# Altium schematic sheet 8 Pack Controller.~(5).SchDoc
size B; PageSetup: Record=PageOptions|CenterHorizontal=True|CenterVertical=True|PrintScale=1.09|XCorrection=1.00|YCorrection=1.00|PrintKind=0|BorderSize=5000000|LeftOffset=0|BottomOffset=0|Orientation=2|PaperLength=1000|PaperWidth=1000|Scale=100|PaperSource=15|PrintQuality=600|MediaType=1|DitherType=10|PaperKind=11x17|PrintScaleMode=1
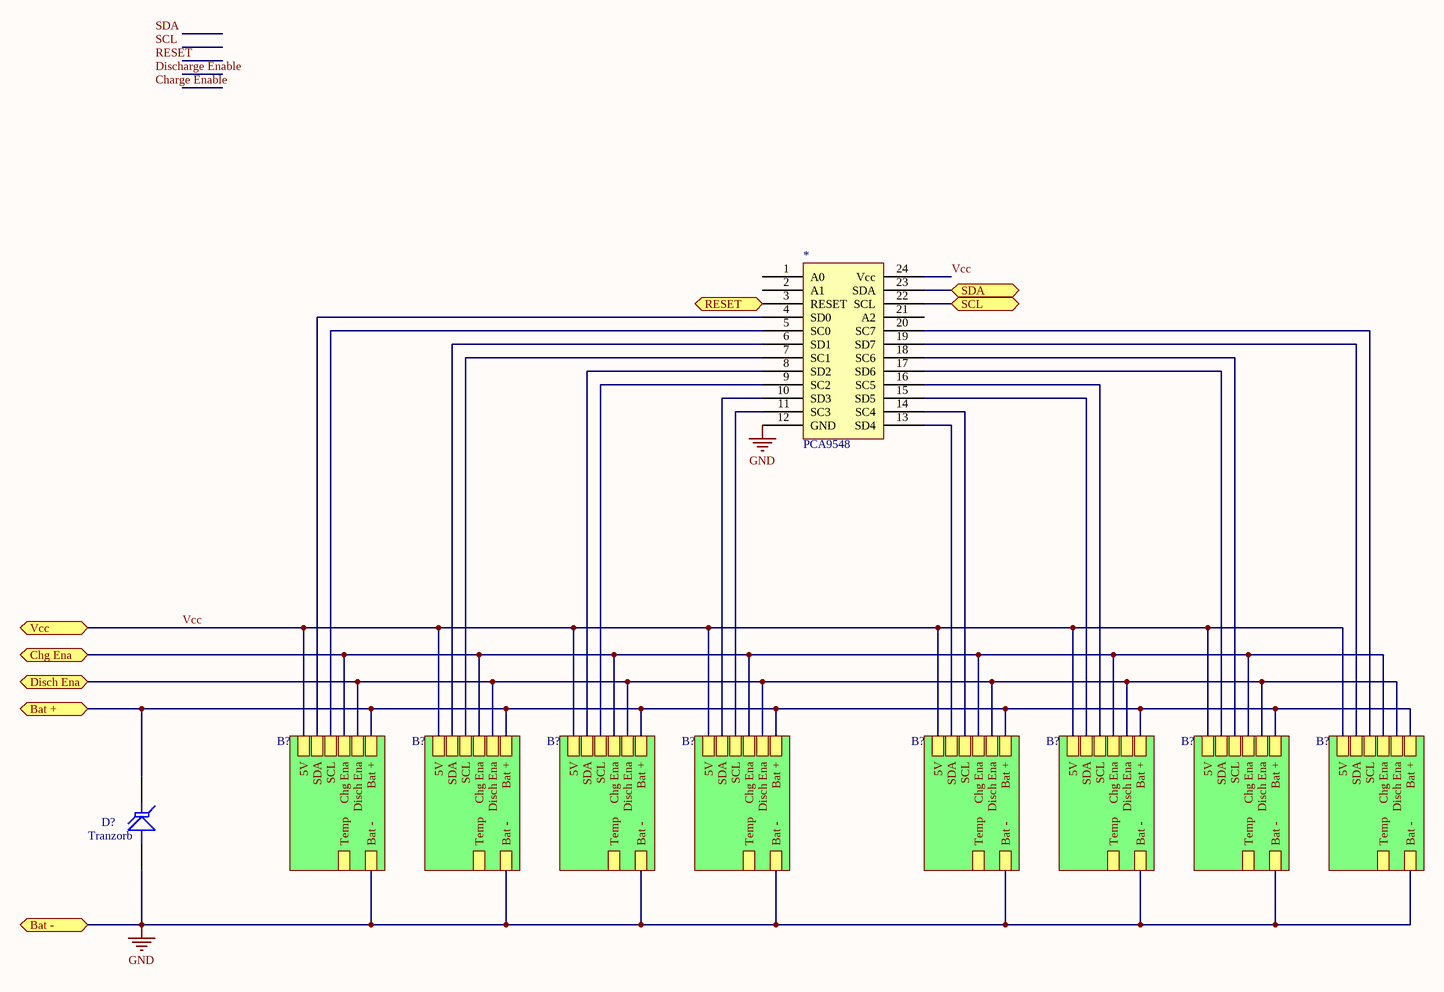
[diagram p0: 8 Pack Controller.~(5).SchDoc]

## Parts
*  PCA9548
D?  Tranzorb  [DIO10.2-7x2.7]

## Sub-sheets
B? = Single Pack Control.SchDoc: Disch Ena, Bat +, Chg Ena, Bat -, SCL, SDA, 5V, Temp
B? = Single Pack Control.SchDoc: Disch Ena, Bat +, Chg Ena, Bat -, SCL, SDA, 5V, Temp
B? = Single Pack Control.SchDoc: Disch Ena, Bat +, Chg Ena, Bat -, SCL, SDA, 5V, Temp
B? = Single Pack Control.SchDoc: Disch Ena, Bat +, Chg Ena, Bat -, SCL, SDA, 5V, Temp
B? = Single Pack Control.SchDoc: Disch Ena, Bat +, Chg Ena, Bat -, SCL, SDA, 5V, Temp
B? = Single Pack Control.SchDoc: Disch Ena, Bat +, Chg Ena, Bat -, SCL, SDA, 5V, Temp
B? = Single Pack Control.SchDoc: Disch Ena, Bat +, Chg Ena, Bat -, SCL, SDA, 5V, Temp
B? = Single Pack Control.SchDoc: Disch Ena, Bat +, Chg Ena, Bat -, SCL, SDA, 5V, Temp

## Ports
Bat +, Bat - (bidir), Chg Ena, Disch Ena, RESET (in), SCL, SDA, Vcc

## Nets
GND: *.12(GND) D?.1(A) ; port Bat -, sheet B?/Bat -, sheet B?/Bat -, sheet B?/Bat -, sheet B?/Bat -, sheet B?/Bat -, sheet B?/Bat -, sheet B?/Bat -, sheet B?/Bat -
Bat +: D?.2(K) ; port Bat +, sheet B?/Bat +, sheet B?/Bat +, sheet B?/Bat +, sheet B?/Bat +, sheet B?/Bat +, sheet B?/Bat +, sheet B?/Bat +, sheet B?/Bat +
Chg Ena: port Chg Ena, sheet B?/Chg Ena, sheet B?/Chg Ena, sheet B?/Chg Ena, sheet B?/Chg Ena, sheet B?/Chg Ena, sheet B?/Chg Ena, sheet B?/Chg Ena, sheet B?/Chg Ena
Disch Ena: port Disch Ena, sheet B?/Disch Ena, sheet B?/Disch Ena, sheet B?/Disch Ena, sheet B?/Disch Ena, sheet B?/Disch Ena, sheet B?/Disch Ena, sheet B?/Disch Ena, sheet B?/Disch Ena
RESET: *.3(RESET) ; port RESET
SCL: *.22(SCL) ; port SCL
SDA: *.23(SDA) ; port SDA
Vcc: *.24(Vcc) ; port Vcc, sheet B?/5V, sheet B?/5V, sheet B?/5V, sheet B?/5V, sheet B?/5V, sheet B?/5V, sheet B?/5V, sheet B?/5V
Net*_4: *.4(SD0) ; sheet B?/SDA
Net*_5: *.5(SC0) ; sheet B?/SCL
Net*_6: *.6(SD1) ; sheet B?/SDA
Net*_7: *.7(SC1) ; sheet B?/SCL
Net*_8: *.8(SD2) ; sheet B?/SDA
Net*_9: *.9(SC2) ; sheet B?/SCL
Net*_10: *.10(SD3) ; sheet B?/SDA
Net*_11: *.11(SC3) ; sheet B?/SCL
Net*_13: *.13(SD4) ; sheet B?/SDA
Net*_14: *.14(SC4) ; sheet B?/SCL
Net*_15: *.15(SD5) ; sheet B?/SDA
Net*_16: *.16(SC5) ; sheet B?/SCL
Net*_17: *.17(SD6) ; sheet B?/SDA
Net*_18: *.18(SC6) ; sheet B?/SCL
Net*_19: *.19(SD7) ; sheet B?/SDA
Net*_20: *.20(SC7) ; sheet B?/SCL

Not connected (* = marked no-connect by the designer): * 1(A0) 2(A1) 21(A2)

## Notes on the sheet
- Labels drawn without touching a wire or pin: Charge Enable, Discharge Enable, RESET, SCL, SDA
